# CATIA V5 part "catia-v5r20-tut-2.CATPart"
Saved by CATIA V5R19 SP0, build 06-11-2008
Part number: c02tut2
Bounding box of the stored display mesh (mm): x 0 to 0, y -60 to 60, z -50 to 50
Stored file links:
  D:\Shriniwas\v5_r19\Part files\c02\c02tut2.CATPart
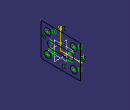
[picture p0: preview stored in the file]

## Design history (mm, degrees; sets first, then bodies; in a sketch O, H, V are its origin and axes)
Body1 (main body)
  Sketch1 on yz-plane, origin (0, 0, 0), H (0, 1, 0), V (0, 0, 1)
    line L1 (-60, -50) -> (60, -50)
    line L2 (60, -50) -> (60, 50)
    line L3 (60, 50) -> (-60, 50)
    line L4 (-60, 50) -> (-60, -50)
    line L5 (-30, 10) -> (30, 10)
    arc A1 centre (30, 0) radius 10 from (30, 10) to (30, -10) cw
    line L6 (30, -10) -> (-30, -10)
    arc A2 centre (-30, 0) radius 10 from (-30, -10) to (-30, 10) cw
    circle A3 centre (40, 30) radius 10
    circle A4 centre (40, -30) radius 10
    circle A5 centre (-40, 30) radius 10
    circle A6 centre (-40, -30) radius 10
    radius A3 = 10
    radius A4 = 10
    radius A5 = 10
    radius A6 = 10
    horizontal: L1 H, L3 H, L5 H
    vertical: L2 V, L4 V
    tangency: A1 L5, L6 A1, A2 L5, A2 L6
